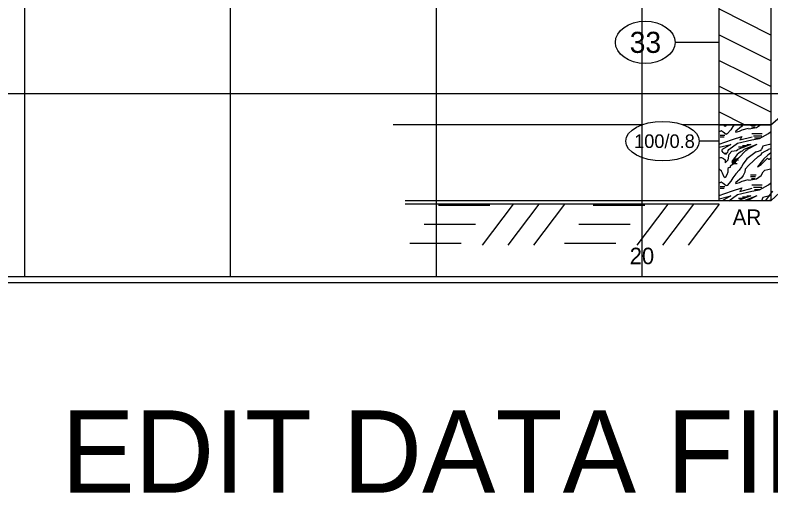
# Model space of a CAD drawing. Extents: x 278618 to 280654, y 171155 to 171855.
# Drawn here: x 280043.65 to 280080.38, y 171178.31 to 171201.56 of the extents above; entities that cross this region are included whole.
import ezdxf

# ---------------------------------------------------------------- set-up
doc = ezdxf.new("R2010")
doc.units = 0
for name, color, linetype in [('Geotech Sheets and Borders Cell', 7, 'Continuous'), ('Prop Road Sect_ Boring - Material (Outline)', 7, 'Continuous'), ('Prop Road Sect_ Boring - Peripheral (HR Indicator)', 7, 'Continuous'), ('Prop Road Sect_ Boring - Peripheral (SPT Oval + Leader)', 7, 'Continuous'), ('Prop Road Sect_ Boring - Peripheral (SPT Tx)', 7, 'Continuous'), ('Prop Road Sect_ Material - Contact (General - Major)', 7, 'Continuous'), ('Prop Strc Sect_ Grid - minor', 7, 'Continuous'), ('Scratch_Level_4', 7, 'Continuous'), ('Sheet Plot Border Inside CELL', 7, 'Continuous'), ('Water Mark (Dry) Cell', 7, 'Continuous')]:
    doc.layers.add(name, color=color, linetype=linetype)

msp = doc.modelspace()

# ---------------------------------------------------------------- linework, layer by layer
at = {"layer": 'Geotech Sheets and Borders Cell'}
msp.add_lwpolyline([(280024.125, 171293.859), (280174.125, 171293.859), (280174.125, 171188.859), (280024.125, 171188.859)], close=True, dxfattribs=at)
at = {"layer": 'Prop Road Sect_ Boring - Material (Outline)'}
for p, q in [((280077.875, 171201.862), (280079.123, 171201.238)), ((280077.875, 171201.862), (280079.123, 171201.238)), ((280079.123, 171201.238), (280080.372, 171200.613)), ((280079.123, 171201.238), (280080.372, 171200.613)), ((280077.875, 171200.613), (280080.372, 171199.365)), ((280077.875, 171200.613), (280080.372, 171199.365)), ((280077.875, 171200.613), (280080.372, 171199.365)), ((280077.875, 171200.613), (280080.372, 171199.365)), ((280080.372, 171200.613), (280080.375, 171200.612)), ((280080.372, 171200.613), (280080.375, 171200.612)), ((280080.372, 171200.613), (280080.375, 171200.612)), ((280080.372, 171200.613), (280080.375, 171200.612)), ((280077.875, 171199.365), (280079.123, 171198.74)), ((280077.875, 171199.365), (280079.123, 171198.74)), ((280080.372, 171199.365), (280080.375, 171199.363)), ((280080.372, 171199.365), (280080.375, 171199.363)), ((280079.123, 171198.74), (280080.372, 171198.116)), ((280079.123, 171198.74), (280080.372, 171198.116)), ((280077.875, 171198.116), (280080.372, 171196.867)), ((280077.875, 171198.116), (280080.372, 171196.867)), ((280077.875, 171198.116), (280080.372, 171196.867)), ((280077.875, 171198.116), (280080.372, 171196.867)), ((280080.372, 171198.116), (280080.375, 171198.115)), ((280080.372, 171198.116), (280080.375, 171198.115)), ((280080.372, 171198.116), (280080.375, 171198.115)), ((280080.372, 171198.116), (280080.375, 171198.115)), ((280077.875, 171196.867), (280079.123, 171196.243)), ((280077.875, 171196.867), (280079.123, 171196.243)), ((280080.372, 171196.867), (280080.375, 171196.866)), ((280080.372, 171196.867), (280080.375, 171196.866)), ((280079.388, 171196.217), (280079.638, 171196.217)), ((280079.388, 171196.217), (280079.638, 171196.217)), ((280079.438, 171196.132), (280079.613, 171196.132)), ((280079.438, 171196.132), (280079.613, 171196.132)), ((280077.913, 171195.738), (280078.138, 171195.738)), ((280077.913, 171195.738), (280078.138, 171195.738)), ((280079.463, 171195.823), (280079.963, 171195.823)), ((280079.463, 171195.823), (280079.963, 171195.823)), ((280079.538, 171195.71), (280079.938, 171195.71)), ((280079.538, 171195.71), (280079.938, 171195.71)), ((280080.375, 171195.901), (280080.372, 171195.9)), ((280080.375, 171195.901), (280080.372, 171195.9)), ((280077.913, 171195.654), (280078.113, 171195.654)), ((280077.913, 171195.654), (280078.113, 171195.654)), ((280079.588, 171195.598), (280079.863, 171195.598)), ((280079.588, 171195.598), (280079.863, 171195.598)), ((280080.372, 171195.305), (280080.375, 171195.306)), ((280080.372, 171195.305), (280080.375, 171195.306)), ((280077.875, 171195.147), (280078.443, 171195.284)), ((280077.875, 171195.147), (280078.443, 171195.284)), ((280078.443, 171195.284), (280078.013, 171195.04)), ((280078.443, 171195.284), (280078.013, 171195.04)), ((280078.313, 171194.984), (280078.334, 171195.04)), ((280078.313, 171194.984), (280078.334, 171195.04)), ((280078.713, 171194.984), (280078.774, 171195.04)), ((280078.713, 171194.984), (280078.774, 171195.04)), ((280079.414, 171195.287), (280078.774, 171195.04)), ((280079.414, 171195.287), (280078.774, 171195.04)), ((280078.813, 171195.166), (280079.099, 171195.166)), ((280078.813, 171195.166), (280079.099, 171195.166)), ((280078.997, 171195.234), (280079.277, 171195.234)), ((280078.997, 171195.234), (280079.277, 171195.234)), ((280079.709, 171195.287), (280079.069, 171195.04)), ((280079.709, 171195.287), (280079.069, 171195.04)), ((280079.163, 171194.984), (280079.232, 171195.04)), ((280079.163, 171194.984), (280079.232, 171195.04)), ((280079.214, 171195.287), (280079.414, 171195.287)), ((280079.214, 171195.287), (280079.414, 171195.287)), ((280079.709, 171195.287), (280079.232, 171195.04)), ((280079.709, 171195.287), (280079.232, 171195.04)), ((280080.372, 171195.07), (280080.259, 171195.04)), ((280080.372, 171195.07), (280080.259, 171195.04)), ((280080.372, 171195.147), (280080.375, 171195.148)), ((280080.372, 171195.147), (280080.375, 171195.148)), ((280080.375, 171194.611), (280080.372, 171194.61)), ((280080.375, 171194.611), (280080.372, 171194.61)), ((280078.496, 171194.427), (280078.681, 171194.427)), ((280078.496, 171194.427), (280078.681, 171194.427)), ((280078.512, 171194.482), (280078.727, 171194.482)), ((280078.512, 171194.482), (280078.727, 171194.482)), ((280078.513, 171194.365), (280078.738, 171194.365)), ((280078.513, 171194.365), (280078.738, 171194.365)), ((280078.543, 171194.529), (280078.811, 171194.529)), ((280078.543, 171194.529), (280078.811, 171194.529)), ((280077.981, 171193.994), (280077.875, 171194.08)), ((280077.981, 171193.994), (280077.875, 171194.08)), ((280080.375, 171194.078), (280080.372, 171194.08)), ((280080.375, 171194.078), (280080.372, 171194.08)), ((280079.388, 171193.803), (280079.663, 171193.803)), ((280079.388, 171193.803), (280079.663, 171193.803)), ((280079.388, 171193.719), (280079.638, 171193.719)), ((280079.388, 171193.719), (280079.638, 171193.719)), ((280079.438, 171193.634), (280079.613, 171193.634)), ((280079.438, 171193.634), (280079.613, 171193.634)), ((280077.913, 171193.24), (280078.138, 171193.24)), ((280077.913, 171193.24), (280078.138, 171193.24)), ((280077.913, 171193.157), (280078.113, 171193.157)), ((280077.913, 171193.157), (280078.113, 171193.157)), ((280079.463, 171193.325), (280079.963, 171193.325)), ((280079.463, 171193.325), (280079.963, 171193.325)), ((280079.538, 171193.213), (280079.938, 171193.213)), ((280079.538, 171193.213), (280079.938, 171193.213)), ((280079.588, 171193.1), (280079.863, 171193.1)), ((280079.588, 171193.1), (280079.863, 171193.1)), ((280080.375, 171193.404), (280080.372, 171193.402)), ((280080.375, 171193.404), (280080.372, 171193.402)), ((280077.875, 171192.65), (280078.443, 171192.787)), ((280077.875, 171192.65), (280078.443, 171192.787)), ((280078.443, 171192.787), (280078.013, 171192.543)), ((280078.443, 171192.787), (280078.013, 171192.543)), ((280079.414, 171192.789), (280078.774, 171192.543)), ((280079.414, 171192.789), (280078.774, 171192.543)), ((280078.997, 171192.737), (280079.277, 171192.737)), ((280078.997, 171192.737), (280079.277, 171192.737)), ((280079.709, 171192.789), (280079.069, 171192.543)), ((280079.709, 171192.789), (280079.069, 171192.543)), ((280079.214, 171192.789), (280079.414, 171192.789)), ((280079.214, 171192.789), (280079.414, 171192.789)), ((280079.709, 171192.789), (280079.232, 171192.543)), ((280079.709, 171192.789), (280079.232, 171192.543)), ((280080.372, 171192.807), (280080.375, 171192.808)), ((280080.372, 171192.807), (280080.375, 171192.808)), ((280078.813, 171192.668), (280079.099, 171192.668)), ((280078.813, 171192.668), (280079.099, 171192.668)), ((280080.372, 171192.572), (280080.259, 171192.543)), ((280080.372, 171192.572), (280080.259, 171192.543)), ((280080.372, 171192.65), (280080.375, 171192.65)), ((280080.372, 171192.65), (280080.375, 171192.65))]:
    msp.add_line(p, q, dxfattribs=at)
for points in [[(280077.875, 171251.243), (280080.375, 171251.243), (280080.375, 171196.243), (280077.875, 171196.243)], [(280077.875, 171196.243), (280080.375, 171196.243), (280080.375, 171192.543), (280077.875, 171192.543)]]:
    msp.add_lwpolyline(points, close=True, dxfattribs=at)
for points in [[(280078.601, 171196.243), (280078.538, 171196.16), (280078.438, 171195.992), (280078.263, 171195.794), (280078.213, 171195.767), (280078.063, 171195.879)], [(280078.601, 171196.243), (280078.538, 171196.16), (280078.438, 171195.992), (280078.263, 171195.794), (280078.213, 171195.767), (280078.063, 171195.879)], [(280078.208, 171196.243), (280078.163, 171196.16), (280078.113, 171196.188), (280078.092, 171196.243)], [(280078.208, 171196.243), (280078.163, 171196.16), (280078.113, 171196.188), (280078.092, 171196.243)], [(280079.018, 171196.243), (280078.963, 171196.16), (280078.688, 171195.935), (280078.663, 171195.907), (280078.688, 171195.879), (280078.863, 171195.935), (280078.988, 171195.992), (280079.288, 171196.075), (280079.313, 171196.048), (280079.688, 171196.104), (280079.873, 171196.243)], [(280079.018, 171196.243), (280078.963, 171196.16), (280078.688, 171195.935), (280078.663, 171195.907), (280078.688, 171195.879), (280078.863, 171195.935), (280078.988, 171195.992), (280079.288, 171196.075), (280079.313, 171196.048), (280079.688, 171196.104), (280079.873, 171196.243)], [(280078.063, 171195.879), (280077.971, 171195.949), (280077.875, 171195.9)], [(280078.063, 171195.879), (280077.971, 171195.949), (280077.875, 171195.9)], [(280077.875, 171195.305), (280078.142, 171195.398), (280078.521, 171195.52), (280078.967, 171195.674), (280078.912, 171195.552), (280078.87, 171195.501), (280079.467, 171195.656)], [(280077.875, 171195.305), (280078.142, 171195.398), (280078.521, 171195.52), (280078.967, 171195.674), (280078.912, 171195.552), (280078.87, 171195.501), (280079.467, 171195.656)], [(280078.334, 171195.04), (280078.763, 171195.344), (280079.463, 171195.513), (280079.838, 171195.569), (280080.263, 171195.823), (280080.372, 171195.902)], [(280078.334, 171195.04), (280078.763, 171195.344), (280079.463, 171195.513), (280079.838, 171195.569), (280080.263, 171195.823), (280080.372, 171195.902)], [(280080.372, 171195.303), (280080.313, 171195.288), (280079.988, 171195.204), (280079.923, 171195.04)], [(280080.372, 171195.303), (280080.313, 171195.288), (280079.988, 171195.204), (280079.923, 171195.04)], [(280079.163, 171194.984), (280078.813, 171194.619), (280078.738, 171194.563), (280078.563, 171194.563), (280078.488, 171194.45), (280078.513, 171194.365), (280078.538, 171194.309), (280078.413, 171194.225), (280078.413, 171194.169), (280078.413, 171194.169), (280078.338, 171194.14), (280078.288, 171194.113), (280078.288, 171193.944), (280078.238, 171193.803), (280078.163, 171193.663), (280078.113, 171193.69), (280078.038, 171193.888), (280077.981, 171193.994)], [(280079.163, 171194.984), (280078.813, 171194.619), (280078.738, 171194.563), (280078.563, 171194.563), (280078.488, 171194.45), (280078.513, 171194.365), (280078.538, 171194.309), (280078.413, 171194.225), (280078.413, 171194.169), (280078.413, 171194.169), (280078.338, 171194.14), (280078.288, 171194.113), (280078.288, 171193.944), (280078.238, 171193.803), (280078.163, 171193.663), (280078.113, 171193.69), (280078.038, 171193.888), (280077.981, 171193.994)], [(280078.063, 171194.9), (280078.013, 171194.957), (280078.013, 171195.04)], [(280078.063, 171194.9), (280078.013, 171194.957), (280078.013, 171195.04)], [(280078.063, 171194.9), (280078.088, 171194.872), (280078.138, 171194.815), (280078.163, 171194.872), (280078.188, 171194.815), (280078.213, 171194.815), (280078.238, 171194.872), (280078.288, 171194.9), (280078.313, 171194.984)], [(280078.063, 171194.9), (280078.088, 171194.872), (280078.138, 171194.815), (280078.163, 171194.872), (280078.188, 171194.815), (280078.213, 171194.815), (280078.238, 171194.872), (280078.288, 171194.9), (280078.313, 171194.984)], [(280078.092, 171194.584), (280078.163, 171194.534), (280078.163, 171194.394), (280078.313, 171194.534), (280078.363, 171194.815), (280078.488, 171194.957), (280078.713, 171194.984)], [(280078.092, 171194.584), (280078.163, 171194.534), (280078.163, 171194.394), (280078.313, 171194.534), (280078.363, 171194.815), (280078.488, 171194.957), (280078.713, 171194.984)], [(280079.069, 171195.04), (280078.982, 171194.96), (280078.935, 171194.937), (280078.822, 171194.865), (280078.748, 171194.789), (280078.635, 171194.652), (280078.563, 171194.563)], [(280079.069, 171195.04), (280078.982, 171194.96), (280078.935, 171194.937), (280078.822, 171194.865), (280078.748, 171194.789), (280078.635, 171194.652), (280078.563, 171194.563)], [(280079.663, 171194.928), (280079.711, 171194.947), (280079.781, 171194.962), (280079.867, 171194.989), (280079.923, 171195.04)], [(280079.663, 171194.928), (280079.711, 171194.947), (280079.781, 171194.962), (280079.867, 171194.989), (280079.923, 171195.04)], [(280079.763, 171194.703), (280079.913, 171194.788), (280079.963, 171194.872), (280080.113, 171194.957), (280080.163, 171194.984)], [(280079.763, 171194.703), (280079.913, 171194.788), (280079.963, 171194.872), (280080.113, 171194.957), (280080.163, 171194.984)], [(280080.163, 171194.984), (280080.196, 171195.002), (280080.259, 171195.04)], [(280080.163, 171194.984), (280080.196, 171195.002), (280080.259, 171195.04)], [(280078.092, 171194.584), (280077.995, 171194.633), (280077.927, 171194.633), (280077.875, 171194.61)], [(280078.092, 171194.584), (280077.995, 171194.633), (280077.927, 171194.633), (280077.875, 171194.61)], [(280079.663, 171194.928), (280079.213, 171194.59), (280079.038, 171194.338), (280078.963, 171194.197), (280078.838, 171194.028), (280078.688, 171193.859), (280078.538, 171193.663), (280078.438, 171193.494), (280078.263, 171193.297), (280078.213, 171193.269), (280078.063, 171193.382)], [(280079.663, 171194.928), (280079.213, 171194.59), (280079.038, 171194.338), (280078.963, 171194.197), (280078.838, 171194.028), (280078.688, 171193.859), (280078.538, 171193.663), (280078.438, 171193.494), (280078.263, 171193.297), (280078.213, 171193.269), (280078.063, 171193.382)], [(280079.763, 171194.703), (280079.313, 171194.282), (280079.138, 171194.084), (280079.113, 171193.944), (280079.038, 171193.775), (280078.963, 171193.663), (280078.688, 171193.438), (280078.663, 171193.409), (280078.688, 171193.382), (280078.863, 171193.438), (280078.988, 171193.494), (280079.288, 171193.578), (280079.313, 171193.55), (280079.688, 171193.607), (280079.913, 171193.775), (280080.011, 171193.95)], [(280079.763, 171194.703), (280079.313, 171194.282), (280079.138, 171194.084), (280079.113, 171193.944), (280079.038, 171193.775), (280078.963, 171193.663), (280078.688, 171193.438), (280078.663, 171193.409), (280078.688, 171193.382), (280078.863, 171193.438), (280078.988, 171193.494), (280079.288, 171193.578), (280079.313, 171193.55), (280079.688, 171193.607), (280079.913, 171193.775), (280080.011, 171193.95)], [(280080.372, 171194.859), (280080.238, 171194.759), (280080.038, 171194.59), (280079.913, 171194.422), (280079.738, 171194.197), (280079.913, 171194.309), (280080.113, 171194.507), (280080.213, 171194.619), (280080.263, 171194.563), (280080.313, 171194.563), (280080.372, 171194.615)], [(280080.372, 171194.859), (280080.238, 171194.759), (280080.038, 171194.59), (280079.913, 171194.422), (280079.738, 171194.197), (280079.913, 171194.309), (280080.113, 171194.507), (280080.213, 171194.619), (280080.263, 171194.563), (280080.313, 171194.563), (280080.372, 171194.615)], [(280080.011, 171193.95), (280080.093, 171194.033), (280080.235, 171194.07), (280080.372, 171194.097)], [(280080.011, 171193.95), (280080.093, 171194.033), (280080.235, 171194.07), (280080.372, 171194.097)], [(280078.063, 171193.382), (280077.971, 171193.452), (280077.875, 171193.402)], [(280078.063, 171193.382), (280077.971, 171193.452), (280077.875, 171193.402)], [(280077.875, 171192.807), (280078.142, 171192.9), (280078.521, 171193.023), (280078.967, 171193.177), (280078.912, 171193.054), (280078.87, 171193.003), (280079.467, 171193.159)], [(280077.875, 171192.807), (280078.142, 171192.9), (280078.521, 171193.023), (280078.967, 171193.177), (280078.912, 171193.054), (280078.87, 171193.003), (280079.467, 171193.159)], [(280078.334, 171192.543), (280078.763, 171192.847), (280079.463, 171193.015), (280079.838, 171193.072), (280080.263, 171193.325), (280080.372, 171193.404)], [(280078.334, 171192.543), (280078.763, 171192.847), (280079.463, 171193.015), (280079.838, 171193.072), (280080.263, 171193.325), (280080.372, 171193.404)], [(280080.372, 171192.805), (280080.313, 171192.79), (280079.988, 171192.707), (280079.923, 171192.543)], [(280080.372, 171192.805), (280080.313, 171192.79), (280079.988, 171192.707), (280079.923, 171192.543)]]:
    msp.add_lwpolyline(points, dxfattribs=at)
at = {"layer": 'Prop Road Sect_ Boring - Peripheral (HR Indicator)'}
msp.add_line((280080.125, 171192.543), (280080.486, 171193.021), dxfattribs=at)
at = {"layer": 'Prop Road Sect_ Boring - Peripheral (SPT Oval + Leader)'}
for p, q in [((280077.875, 171200.243), (280075.725, 171200.243)), ((280077.875, 171195.443), (280076.907, 171195.443)), ((280077.875, 171195.443), (280077.686, 171195.443)), ((280077.875, 171195.443), (280077.686, 171195.443))]:
    msp.add_line(p, q, dxfattribs=at)
for centre, major_axis, ratio in [((280074.275, 171200.243), (1.451, 0), 0.706609), ((280075.118, 171195.443), (1.788, 0), 0.536928)]:
    msp.add_ellipse(centre, major_axis=major_axis, ratio=ratio, dxfattribs=at)
at = {"layer": 'Prop Road Sect_ Material - Contact (General - Major)'}
for p, q in [((280080.375, 171196.243), (280111.875, 171222.743)), ((280080.375, 171192.543), (280111.875, 171222.043)), ((280074.129, 171196.243), (280062.028, 171196.243)), ((280077.875, 171196.243), (280076.108, 171196.243)), ((280077.875, 171192.543), (280062.603, 171192.543)), ((280077.875, 171192.391), (280062.603, 171192.391)), ((280067.851, 171192.391), (280066.347, 171190.398)), ((280069.101, 171192.391), (280067.597, 171190.398)), ((280070.351, 171192.391), (280068.847, 171190.398)), ((280075.375, 171192.391), (280073.871, 171190.398)), ((280076.625, 171192.391), (280075.121, 171190.398)), ((280077.875, 171192.391), (280076.371, 171190.398))]:
    msp.add_line(p, q, dxfattribs=at)
for points in [[(280066.728, 171192.323), (280064.228, 171192.323)], [(280074.252, 171192.323), (280071.752, 171192.323)], [(280066.028, 171191.394), (280063.528, 171191.394)], [(280073.552, 171191.394), (280071.052, 171191.394)], [(280065.328, 171190.466), (280062.828, 171190.466)], [(280072.852, 171190.466), (280070.352, 171190.466)]]:
    msp.add_lwpolyline(points, dxfattribs=at)
at = {"layer": 'Prop Strc Sect_ Grid - minor'}
for p, q in [((280044.125, 171188.859), (280044.125, 171293.859)), ((280054.125, 171188.859), (280054.125, 171293.859)), ((280064.125, 171188.859), (280064.125, 171293.859)), ((280074.125, 171188.859), (280074.125, 171293.859)), ((280174.125, 171197.743), (280024.125, 171197.743))]:
    msp.add_line(p, q, dxfattribs=at)
at = {"layer": 'Sheet Plot Border Inside CELL'}
msp.add_lwpolyline([(280008.608, 171188.575), (280175.375, 171188.575), (280175.375, 171294.142), (280008.608, 171294.142)], close=True, dxfattribs=at)

# ---------------------------------------------------------------- texts
at = {"layer": 'Geotech Sheets and Borders Cell'}
msp.add_text('20', height=0.8, dxfattribs=at).set_placement((280073.521, 171189.469))
at = {"layer": 'Prop Road Sect_ Boring - Peripheral (SPT Tx)'}
for s, height, p in [('33', 1.025, (280073.524, 171199.73)), ('100/0.8', 0.6612, (280073.736, 171195.112))]:
    msp.add_text(s, height=height, dxfattribs=at).set_placement(p)
at = {"layer": 'Scratch_Level_4'}
msp.add_text('EDIT DATA FIELDS FOR STATIONING', height=4.00002, dxfattribs=at).set_placement((280045.896, 171178.37))
at = {"layer": 'Water Mark (Dry) Cell'}
msp.add_text('AR', height=0.75, dxfattribs=at).set_placement((280078.526, 171191.377))

doc.saveas('drawing.dxf')
